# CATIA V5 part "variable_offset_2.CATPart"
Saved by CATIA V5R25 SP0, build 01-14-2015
Part number: Part1
Bounding box of the stored display mesh (mm): x -92.294 to 37.025, y -35 to 35, z -60.324 to 55.06
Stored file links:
  E:\cadcim\GSD_cat_v5-6r2014\Part_files\variable_offset_2.CATPart
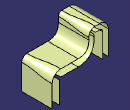
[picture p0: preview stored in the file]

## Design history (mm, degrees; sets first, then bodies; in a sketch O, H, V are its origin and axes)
Set1
  Sketch1 on zx-plane, origin (0, 0, 0), H (-1, 0, 0), V (0, 0, 1)
    point P1 (47.2937, 55.0598)
    line L1 (47.2937, 55.0598) -> (92.2937, 55.0598)
    line L2 (92.2937, 55.0598) -> (92.2937, -19.9402)
    length L2 = 75
    length L1 = 45
    horizontal: L1 H
    vertical: L2 V
  Extrude1: Lim1 35, Lim2 35, Element1 Sketch1
  Sketch2 on zx-plane, origin (0, 0, 0), H (-1, 0, 0), V (0, 0, 1)
    point P1 (47.2937, 55.0598)
    line L1 (47.2937, 55.0598) -> (47.2937, 35.0598)
    reference projected point E1 (47.2937, 55.0598) from Sketch1.P1
    length L1 = 20
    vertical: L1 V
    coincidence: P1 E1
  Extrude2: Lim1 35, Lim2 35, Element1 Sketch2
  Sketch3 on zx-plane, origin (0, 0, 0), H (-1, 0, 0), V (0, 0, 1)
    line L1 (22.975, 9.6765) -> (-37.025, 9.6765)
    line L2 (-37.025, 9.6765) -> (-37.025, -60.3235)
    length L1 = 60
    length L2 = 70
    horizontal: L1 H
    vertical: L2 V
  Extrude3: Lim1 35, Lim2 35, Element1 Sketch3
  Blend1: StartLimit {blendlimit Curve edge of Extrude2, Support Extrude2}, EndLimit {blendlimit Curve edge of Extrude3, Support Extrude3}
  Fillet1: radius 20, on edge [face of Extrude1 from Sketch1.L2 | face of Extrude1 from Sketch1.L1]
  Join1: Elements (Extrude2; Fillet1)
  Fillet2: radius 8, on edge [face of Extrude1 from Sketch1.L1 | face of Extrude2 from Sketch2.L1]
  Fillet3: radius 15, on edge [face of Extrude3 from Sketch3.L1 | face of Extrude3 from Sketch3.L2]
  Join2: Elements (Fillet3; Blend1; Fillet2)
  GSOVariableOffset1: GlobalSurface Join2, ListOfConstraints Blend1, TrickyFaces (face of Fillet2; face of Fillet3)
Body1 (main body)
